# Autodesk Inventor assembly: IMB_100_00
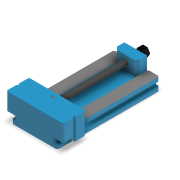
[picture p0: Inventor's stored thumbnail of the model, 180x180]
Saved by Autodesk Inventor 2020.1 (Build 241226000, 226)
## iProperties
Created: 2011-02
Part Number: IMB_100_00
Document SubType Name: Assembly
Designer: F.Stasiak
Mass: 805.102 g
Surface Area: 770.589 cm^2
Volume: 414.829 cm^3
Density: 1.94081 g/cm^3
Company: Fabian Stasiak CAD Consulting
Manager: www.cadconsulting.pl
Author: F.Stasiak
Subject: Zbiór ćwiczeń. Autodesk Inventor 2020. Kurs podstawowy
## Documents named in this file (7)
- C:\2020_Kurs_podstawowy\R1 Pierwszy projekt\Imak 100\IMB_100_00.iam
- C:\2020_Kurs_podstawowy\R1 Pierwszy projekt\Imak 100\IMB_100_01.ipt
- C:\2020_Kurs_podstawowy\R1 Pierwszy projekt\Imak 100\IMB_100_02.ipt
- C:\2020_Kurs_podstawowy\R1 Pierwszy projekt\Imak 100\IMB_100_03.ipt
- C:\2020_Kurs_podstawowy\R1 Pierwszy projekt\Imak 100\IMB_100_04.ipt
- C:\2020_Kurs_podstawowy\Zasoby\Content Center Files\pl-PL\ISO 7435(2)\ISO 7435 - M5 x 10ISO.ipt
- C:\2020_Kurs_podstawowy\Zasoby\Content Center Files\pl-PL\ISO 4762(2)\ISO 4762 - M6 x 25ISO.ipt
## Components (6 placed, 6 different names)
1. IMB_100_01:1 — OBRÓT ŚRUBY, Zestawiający:1, Zestawiający:2, Zestawiający:3, Równoległy:1
2. IMB_100_02:1 — Zestawiający:1, Zestawiający:2, Zestawiający:3, Zestawiający:4, Kąt:1, Obrót/przesunięcie:1, Zestawiający:7
3. IMB_100_03:1 — Równoległy:1, Zestawiający:6
4. IMB_100_04:1 — Równoległy:2, Zestawiający:6, Obrót/przesunięcie:1, Zestawiający:7, OBRÓT ŚRUBY
5. ISO 7435 M5 x 10:1
6. ISO 4762 M6 x 25:1
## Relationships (11: Mate 6, Angle 2, Flush 2, RelateRotateTranslate 1)
- OBRÓT ŚRUBY [Angle]: IMB_100_01:1 ↔ IMB_100_04:1
- Zestawiający:1 [Mate]: IMB_100_01:1 ↔ IMB_100_02:1
- Zestawiający:2 [Mate]: IMB_100_01:1 ↔ IMB_100_02:1
- Zestawiający:3 [Mate]: IMB_100_01:1 ↔ IMB_100_02:1
- Równoległy:1 [Flush]: IMB_100_01:1 ↔ IMB_100_03:1
- Zestawiający:4 [Mate]: IMB_100_02:1
- Kąt:1 [Angle]: IMB_100_02:1
- Równoległy:2 [Flush]: IMB_100_04:1
- Zestawiający:6 [Mate]: IMB_100_03:1 ↔ IMB_100_04:1
- Obrót/przesunięcie:1 [RelateRotateTranslate]: IMB_100_02:1 ↔ IMB_100_04:1
- Zestawiający:7 [Mate]: IMB_100_02:1 ↔ IMB_100_04:1
